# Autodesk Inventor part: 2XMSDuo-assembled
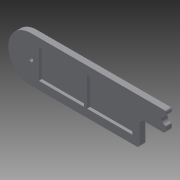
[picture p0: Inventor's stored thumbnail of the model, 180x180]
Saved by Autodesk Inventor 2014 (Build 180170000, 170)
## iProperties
Created: 2015-01
Part Number: 2XMSDuo-assembled
Material: Generic
Document SubType Name: Modeling
Designer: Drano
Density: 1 g/cm^3
Appearance: Default
Author: Drano
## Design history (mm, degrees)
derived "2XMSDuo.iam"
body "Solid1"
node "backplate.ipt:1" dims "d0" = 10
node "2XMSduo.ipt:1" dims "d0" = 10
node "2XMSDuo.iam_Bodies" dims "d0" = 10
